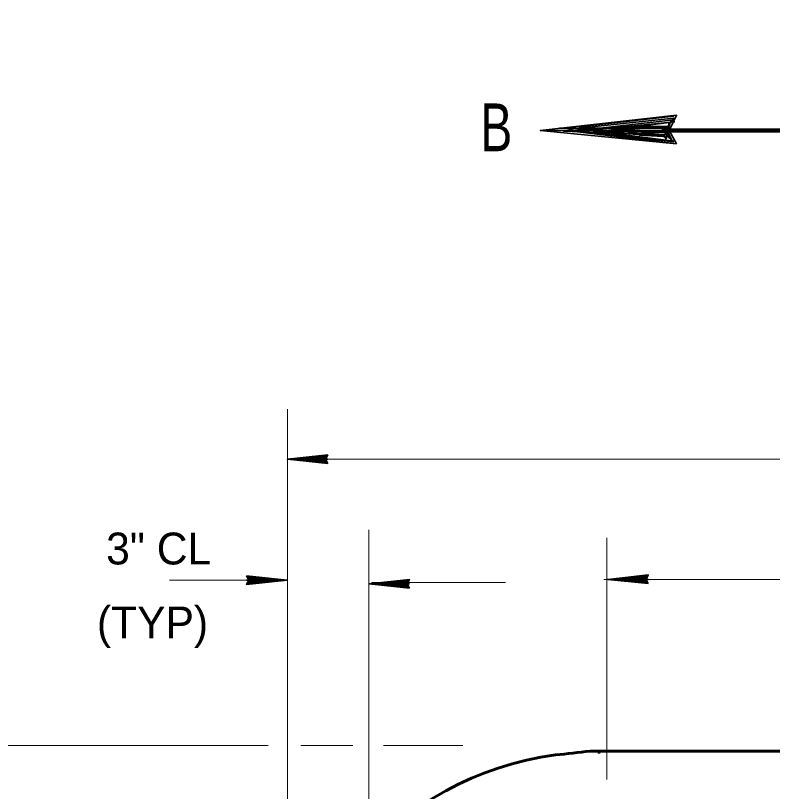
# Model space of a CAD drawing. Extents: x 14.14 to 17.34, y -1.61 to 0.38.
# Drawn here: x 14.4524 to 14.6504, y -0.42 to -0.217 of the extents above; entities that cross this region are included whole.
import ezdxf

# ---------------------------------------------------------------- set-up
doc = ezdxf.new("R2010")
doc.units = 0
doc.header["$LTSCALE"] = 0.0033
doc.layers.add('1', color=7, linetype='Continuous', lineweight=40)

msp = doc.modelspace()

# ---------------------------------------------------------------- linework, layer by layer
at = {"layer": '1', "lineweight": 35}
for p, q in [((14.624583, -0.243333), (14.599833, -0.246083)), ((14.624583, -0.243833), (14.599833, -0.2465)), ((14.624583, -0.24425), (14.599833, -0.247083)), ((14.624833, -0.244833), (14.599917, -0.24725)), ((14.625333, -0.247083), (14.589667, -0.247083)), ((14.624583, -0.249833), (14.598, -0.2465)), ((14.624583, -0.249833), (14.598, -0.247083)), ((14.624583, -0.2505), (14.598, -0.24725)), ((14.624583, -0.2505), (14.598, -0.24725)), ((14.624583, -0.250083), (14.598, -0.24725)), ((14.533833, -0.332), (14.5265, -0.332833)), ((14.533833, -0.332167), (14.5265, -0.332917)), ((14.533833, -0.33225), (14.5265, -0.333083)), ((14.533917, -0.332417), (14.526583, -0.333167)), ((14.534083, -0.333083), (14.5235, -0.333083)), ((14.533833, -0.333917), (14.526, -0.332917)), ((14.533833, -0.333917), (14.526, -0.333083)), ((14.533833, -0.334083), (14.526, -0.333167)), ((14.533833, -0.334083), (14.526, -0.333167)), ((14.533833, -0.334), (14.526, -0.333167)), ((14.512833, -0.364667), (14.523417, -0.364667)), ((14.513, -0.365333), (14.520333, -0.364583)), ((14.513083, -0.363667), (14.520917, -0.364583)), ((14.513083, -0.363667), (14.520917, -0.364583)), ((14.513083, -0.36375), (14.520917, -0.364583)), ((14.513083, -0.363833), (14.520917, -0.364667)), ((14.513083, -0.363833), (14.520917, -0.364833)), ((14.513083, -0.3655), (14.520417, -0.364667)), ((14.513083, -0.365583), (14.520417, -0.364833)), ((14.513083, -0.36575), (14.520417, -0.364917)), ((14.555167, -0.364583), (14.547833, -0.365417)), ((14.555167, -0.36475), (14.547833, -0.3655)), ((14.555167, -0.364833), (14.547833, -0.365667)), ((14.55525, -0.365), (14.547917, -0.36575)), ((14.617917, -0.3645), (14.607333, -0.3645)), ((14.617667, -0.365333), (14.609833, -0.364333)), ((14.617667, -0.365333), (14.609833, -0.3645)), ((14.617667, -0.3655), (14.609833, -0.364583)), ((14.617667, -0.3655), (14.609833, -0.364583)), ((14.617667, -0.365417), (14.609833, -0.364583)), ((14.617667, -0.363417), (14.610333, -0.36425)), ((14.617667, -0.363583), (14.610333, -0.364333)), ((14.617667, -0.363667), (14.610333, -0.3645)), ((14.61775, -0.363833), (14.610417, -0.364583)), ((14.555417, -0.365667), (14.544833, -0.365667)), ((14.555167, -0.3665), (14.547333, -0.3655)), ((14.555167, -0.3665), (14.547333, -0.365667)), ((14.555167, -0.366667), (14.547333, -0.36575)), ((14.555167, -0.366667), (14.547333, -0.36575)), ((14.555167, -0.366583), (14.547333, -0.36575))]:
    msp.add_line(p, q, dxfattribs=at)
at = {"layer": '1', "lineweight": 13}
for p, q in [((14.5235, -0.456083), (14.5235, -0.32)), ((14.523417, -0.333083), (14.983333, -0.333083)), ((14.544833, -0.457417), (14.544833, -0.3515)), ((14.607083, -0.416833), (14.607083, -0.353583)), ((14.492667, -0.364667), (14.5135, -0.364667)), ((14.5455, -0.365333), (14.580583, -0.365333)), ((14.606333, -0.3645), (15.022333, -0.3645)), ((14.423667, -0.407917), (14.5185, -0.407917)), ((14.527, -0.407917), (14.540667, -0.407917)), ((14.548667, -0.407917), (14.569417, -0.407917)), ((14.5235, -0.409417), (14.5235, -0.409333))]:
    msp.add_line(p, q, dxfattribs=at)
at = {"layer": '1', "lineweight": 60}
for p, q in [((14.740667, -0.409417), (14.60275, -0.409417)), ((14.6465, -0.409417), (14.98225, -0.409417))]:
    msp.add_line(p, q, dxfattribs=at)
at = {"layer": '1', "lineweight": 90}
msp.add_lwpolyline([(14.663167, -0.217), (14.663167, -0.247083), (14.6215, -0.247083)], dxfattribs=at)
at = {"layer": '1', "lineweight": 35}
for points in [[(14.625333, -0.250583), (14.589667, -0.247083), (14.625333, -0.243083), (14.623417, -0.247083)], [(14.622917, -0.24725), (14.607083, -0.247583), (14.607083, -0.24725), (14.610083, -0.24725), (14.622917, -0.247583), (14.612667, -0.247833), (14.623417, -0.24825), (14.615667, -0.248333), (14.623417, -0.24875), (14.611583, -0.247833), (14.59575, -0.24725), (14.598833, -0.2465), (14.594667, -0.2465), (14.622917, -0.2465), (14.614583, -0.246), (14.623417, -0.246), (14.605417, -0.24725), (14.623417, -0.245)], [(14.534083, -0.334167), (14.5235, -0.333083), (14.534083, -0.331917), (14.5335, -0.333083)], [(14.533333, -0.333167), (14.528667, -0.33325), (14.528667, -0.333167), (14.529583, -0.333167), (14.533333, -0.33325), (14.530333, -0.333333), (14.5335, -0.333417), (14.53125, -0.3335), (14.5335, -0.333583), (14.53, -0.333333), (14.525333, -0.333167), (14.52625, -0.332917), (14.525, -0.332917), (14.533333, -0.332917), (14.530917, -0.33275), (14.5335, -0.33275), (14.528167, -0.333167), (14.5335, -0.3325)], [(14.512833, -0.363583), (14.523417, -0.364667), (14.512833, -0.365833), (14.513417, -0.364667)], [(14.513583, -0.364583), (14.51825, -0.3645), (14.51825, -0.364583), (14.517333, -0.364583), (14.513583, -0.3645), (14.516583, -0.364417), (14.513417, -0.364333), (14.515667, -0.36425), (14.513417, -0.364167), (14.516917, -0.364417), (14.521583, -0.364583), (14.520667, -0.364833), (14.521917, -0.364833), (14.513583, -0.364833), (14.516, -0.365), (14.513417, -0.365), (14.51875, -0.364583), (14.513417, -0.36525)], [(14.555417, -0.36675), (14.544833, -0.365667), (14.555417, -0.3645), (14.554833, -0.365667)], [(14.554667, -0.36575), (14.55, -0.365833), (14.55, -0.36575), (14.550917, -0.36575), (14.554667, -0.365833), (14.551667, -0.365917), (14.554833, -0.366), (14.552583, -0.366083), (14.554833, -0.366167), (14.551333, -0.365917), (14.546667, -0.36575), (14.547583, -0.3655), (14.546333, -0.3655), (14.554667, -0.3655), (14.55225, -0.365333), (14.554833, -0.365333), (14.5495, -0.36575), (14.554833, -0.365083)], [(14.617917, -0.365583), (14.607333, -0.3645), (14.617917, -0.363333), (14.617333, -0.3645)], [(14.617167, -0.364583), (14.6125, -0.364667), (14.6125, -0.364583), (14.613417, -0.364583), (14.617167, -0.364667), (14.614167, -0.36475), (14.617333, -0.364833), (14.615083, -0.364917), (14.617333, -0.365), (14.613833, -0.36475), (14.609167, -0.364583), (14.610083, -0.364333), (14.608833, -0.364333), (14.617167, -0.364333), (14.61475, -0.364167), (14.617333, -0.364167), (14.612, -0.364583), (14.617333, -0.363917)]]:
    msp.add_lwpolyline(points, close=True, dxfattribs=at)
for points in [[(14.622917, -0.24725), (14.624167, -0.249833), (14.623417, -0.249), (14.622917, -0.247833), (14.621917, -0.24825), (14.622583, -0.249333), (14.623083, -0.24675), (14.623667, -0.245), (14.624583, -0.24375)], [(14.533333, -0.333167), (14.53375, -0.333917), (14.5335, -0.333667), (14.533333, -0.333333), (14.533083, -0.333417), (14.53325, -0.33375), (14.533417, -0.333), (14.533583, -0.3325), (14.533833, -0.332083)], [(14.513583, -0.364583), (14.513167, -0.363833), (14.513417, -0.364083), (14.513583, -0.364417), (14.513833, -0.364333), (14.513667, -0.364), (14.5135, -0.36475), (14.513333, -0.36525), (14.513083, -0.365667)], [(14.554667, -0.36575), (14.555083, -0.3665), (14.554833, -0.36625), (14.554667, -0.365917), (14.554417, -0.366), (14.554583, -0.366333), (14.55475, -0.365583), (14.554917, -0.365083), (14.555167, -0.364667)], [(14.617167, -0.364583), (14.617583, -0.365333), (14.617333, -0.365083), (14.617167, -0.36475), (14.616917, -0.364833), (14.617083, -0.365167), (14.61725, -0.364417), (14.617417, -0.363917), (14.617667, -0.3635)]]:
    msp.add_lwpolyline(points, dxfattribs=at)
at = {"layer": '1', "lineweight": 60}
for centre, radius, start, end in [((14.516271, 0.334349), 0.748776, 275.93287, 276.63212), ((14.604667, -0.4925), 0.082833, 89.52055, 89.94236), ((14.604667, -0.4925), 0.082833, 97.64809, 263.01663)]:
    msp.add_arc(centre, radius, start, end, dxfattribs=at)

# ---------------------------------------------------------------- texts
at = {"layer": '1', "width": 0.75}
msp.add_text('B', height=0.0125, dxfattribs=at).set_placement((14.574, -0.2525))
at = {"layer": '1'}
for s, p in [('3" CL', (14.476083, -0.360583)), ('(TYP)', (14.473667, -0.379917))]:
    msp.add_text(s, height=0.008334, dxfattribs=at).set_placement(p)

doc.saveas('drawing.dxf')
